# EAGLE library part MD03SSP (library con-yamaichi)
YAMAICHI CONNECTOR
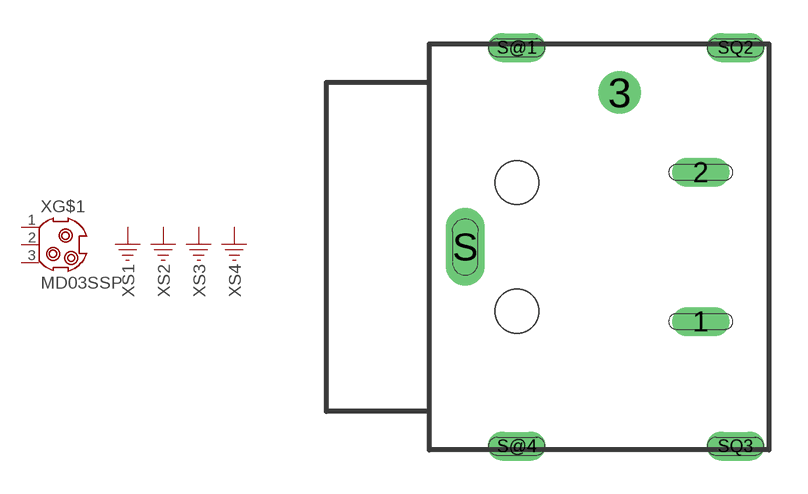
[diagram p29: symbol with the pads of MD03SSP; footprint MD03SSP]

Designator prefix X; gates G$1=MD03SSP S1=SHIELD S2=SHIELD S3=SHIELD S4=SHIELD

## MD03SSP (OC_FARNELL: unknown; OC_NEWARK: unknown)  [MD03SSP]
1  G$1:1  pas
2  G$1:2  pas
3  G$1:3  pas
S@1  S4:1  pas
S@4  S3:1  pas
SQ2  S2:1  pas
SQ3  S1:1  pas

## Footprint MD03SSP (pad centres in mm)
Mini Din YAMAICHI CONNECTOR
drill 0.61 long: 1 3.65,-2.9; 2 3.65,2.9; S@1 -3.5,7.75; S@4 -3.5,-7.75; SQ2 5,7.75; SQ3 5,-7.75
drill 1.1 round: 3 0.5,6
drill 1 long: S -5.5,0
hole 1.7 at -3.5,-2.5
hole 1.7 at -3.5,2.5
